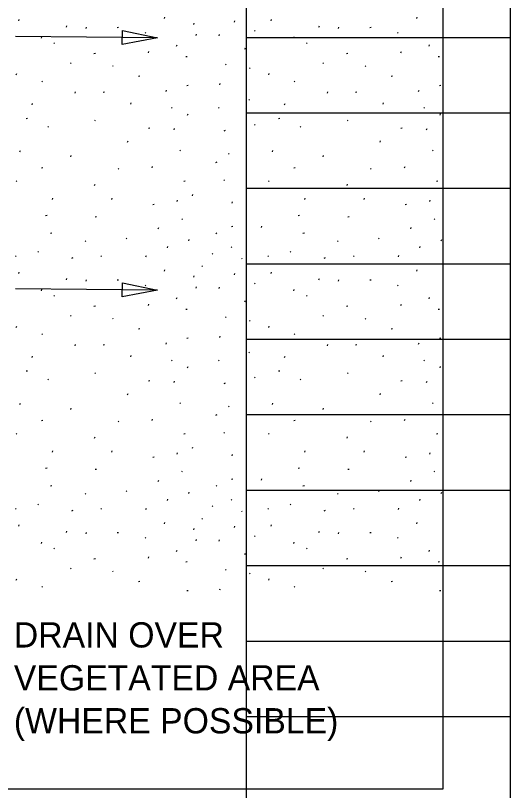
# Model space of a CAD drawing. Extents: x 0 to 34, y 0 to 22.
# Drawn here: x 8.482 to 10.32, y 5.465 to 8.341 of the extents above; entities that cross this region are included whole.
import ezdxf

# ---------------------------------------------------------------- set-up
doc = ezdxf.new("R2010")
doc.units = 0
for name, color, linetype in [('PF_P_Text', 7, 'Continuous'), ('SC_Scratch1', 7, 'Continuous'), ('SH_Text', 7, 'Continuous')]:
    doc.layers.add(name, color=color, linetype=linetype)

msp = doc.modelspace()

# ---------------------------------------------------------------- linework, layer by layer
at = {"layer": 'SC_Scratch1'}
for p, q in [((9.34, 0.98), (9.34, 21.14)), ((10.32, 0.98), (10.32, 21.14)), ((9.34, 8.26), (10.32, 8.26)), ((9.34, 7.98), (10.32, 7.98)), ((9.34, 7.7), (10.32, 7.7)), ((9.34, 7.42), (10.32, 7.42)), ((9.34, 7.14), (10.32, 7.14)), ((9.34, 6.86), (10.32, 6.86)), ((9.34, 6.58), (10.32, 6.58)), ((9.34, 6.3), (10.32, 6.3)), ((9.34, 6.02), (10.32, 6.02)), ((9.34, 5.74), (10.32, 5.74))]:
    msp.add_line(p, q, dxfattribs=at)
at = {"layer": 'SH_Text'}
for p, q in [((8.4939, 8.3209), (8.4956, 8.3258)), ((9.0346, 8.33), (9.0363, 8.3348)), ((9.1437, 8.3073), (9.1453, 8.3122)), ((9.2951, 8.3164), (9.2967, 8.3212)), ((9.4314, 8.3209), (9.433, 8.3258)), ((9.9721, 8.33), (9.9738, 8.3348)), ((8.6711, 8.2982), (8.6728, 8.3031)), ((8.7437, 8.2929), (8.7454, 8.2978)), ((8.8646, 8.2971), (8.8596, 8.296)), ((9.3714, 8.2829), (9.369, 8.2853)), ((9.6086, 8.2982), (9.6103, 8.3031)), ((9.6812, 8.2929), (9.6829, 8.2978)), ((9.8021, 8.2971), (9.7971, 8.296)), ((9.0096, 8.2582), (8.4817, 8.2629)), ((8.5779, 8.2567), (8.5795, 8.2615)), ((8.9655, 8.2761), (8.9631, 8.2786)), ((9.1528, 8.2665), (9.1544, 8.2714)), ((9.2382, 8.2657), (9.2399, 8.2706)), ((9.5154, 8.2567), (9.517, 8.2615)), ((9.903, 8.2761), (9.9006, 8.2786)), ((8.627, 8.2376), (8.6246, 8.24)), ((9.08, 8.2272), (9.0816, 8.2321)), ((9.5645, 8.2376), (9.5621, 8.24)), ((10.0175, 8.2272), (10.0191, 8.2321)), ((8.7783, 8.1997), (8.7732, 8.1986)), ((8.9755, 8.2023), (8.9771, 8.2071)), ((9.3336, 8.2159), (9.3353, 8.2207)), ((9.7158, 8.1997), (9.7107, 8.1986)), ((9.913, 8.2023), (9.9146, 8.2071)), ((9.1191, 8.1883), (9.114, 8.1872)), ((10.0566, 8.1883), (10.0515, 8.1872)), ((8.6884, 8.1628), (8.6859, 8.1652)), ((8.8451, 8.1514), (8.8427, 8.1539)), ((9.2646, 8.1582), (9.2622, 8.1607)), ((9.3532, 8.1446), (9.3508, 8.1471)), ((9.6259, 8.1628), (9.6234, 8.1652)), ((9.7826, 8.1514), (9.7802, 8.1539)), ((8.4847, 8.1207), (8.4864, 8.1255)), ((8.9441, 8.1158), (8.9391, 8.1147)), ((9.4222, 8.1207), (9.4239, 8.1255)), ((9.8816, 8.1158), (9.8766, 8.1147)), ((8.5816, 8.0948), (8.5791, 8.0972)), ((9.1236, 8.0818), (9.1186, 8.0807)), ((9.2405, 8.0844), (9.2421, 8.0893)), ((9.5191, 8.0948), (9.5166, 8.0972)), ((10.0611, 8.0818), (10.0561, 8.0807)), ((8.7028, 8.0527), (8.7045, 8.0575)), ((8.8123, 8.0569), (8.8073, 8.0558)), ((9.0414, 8.0595), (9.043, 8.0643)), ((9.6403, 8.0527), (9.642, 8.0575)), ((9.7498, 8.0569), (9.7448, 8.0558)), ((9.9789, 8.0595), (9.9805, 8.0643)), ((9.351, 8.0268), (9.3485, 8.0292)), ((8.5438, 8.0096), (8.5454, 8.0145)), ((8.9096, 8.0119), (8.9112, 8.0167)), ((9.0632, 7.9973), (9.0608, 7.9997)), ((9.2387, 7.9969), (9.2362, 7.9993)), ((9.4813, 8.0096), (9.4829, 8.0145)), ((9.8471, 8.0119), (9.8487, 8.0167)), ((10.0007, 7.9973), (9.9983, 7.9997)), ((9.121, 7.9718), (9.1226, 7.9767)), ((10.0585, 7.9718), (10.0601, 7.9767)), ((8.5261, 7.9594), (8.5211, 7.9583)), ((8.7792, 7.9497), (8.7768, 7.9521)), ((9.4636, 7.9594), (9.4586, 7.9583)), ((9.7167, 7.9497), (9.7143, 7.9521)), ((8.6043, 7.927), (8.6019, 7.9295)), ((8.9805, 7.9231), (8.9754, 7.922)), ((9.0709, 7.9167), (9.0725, 7.9215)), ((9.2607, 7.914), (9.2558, 7.9116)), ((9.3714, 7.9338), (9.369, 7.9363)), ((9.5418, 7.927), (9.5394, 7.9295)), ((9.918, 7.9231), (9.9129, 7.922)), ((10.0084, 7.9167), (10.01, 7.9215)), ((8.8982, 7.8713), (8.8999, 7.8762)), ((9.8357, 7.8713), (9.8374, 7.8762)), ((8.4984, 7.8351), (8.5, 7.8399)), ((9.095, 7.8386), (9.0926, 7.8411)), ((9.2753, 7.8264), (9.2729, 7.8288)), ((9.4359, 7.8351), (9.4375, 7.8399)), ((10.0325, 7.8386), (10.0301, 7.8411)), ((8.6869, 7.8169), (8.6886, 7.8218)), ((9.2289, 7.7971), (9.224, 7.7947)), ((9.6244, 7.8169), (9.6261, 7.8218)), ((8.5829, 7.7758), (8.5779, 7.7747)), ((8.8656, 7.7706), (8.8631, 7.7731)), ((8.9891, 7.7761), (8.9907, 7.781)), ((9.5204, 7.7758), (9.5154, 7.7747)), ((9.8031, 7.7706), (9.8006, 7.7731)), ((9.9266, 7.7761), (9.9282, 7.781)), ((8.4862, 7.7253), (8.4837, 7.7277)), ((8.7755, 7.7104), (8.7772, 7.7153)), ((9.1122, 7.7259), (9.1072, 7.7248)), ((9.2582, 7.7289), (9.2558, 7.7314)), ((9.4237, 7.7253), (9.4212, 7.7277)), ((9.713, 7.7104), (9.7147, 7.7153)), ((10.0497, 7.7259), (10.0447, 7.7248)), ((8.6188, 7.6583), (8.6204, 7.6631)), ((8.8392, 7.6583), (8.8408, 7.6631)), ((9.0823, 7.6515), (9.0839, 7.6563)), ((9.1391, 7.6726), (9.1408, 7.6775)), ((9.5563, 7.6583), (9.5579, 7.6631)), ((9.7767, 7.6583), (9.7783, 7.6631)), ((10.0198, 7.6515), (10.0214, 7.6563)), ((8.9964, 7.6398), (8.9914, 7.6387)), ((9.2859, 7.6447), (9.2876, 7.6495)), ((9.9339, 7.6398), (9.9288, 7.6387)), ((8.5988, 7.599), (8.5938, 7.5979)), ((8.7828, 7.5944), (8.7778, 7.5934)), ((9.5363, 7.599), (9.5313, 7.5979)), ((9.7203, 7.5944), (9.7153, 7.5934)), ((9.1018, 7.5848), (9.0994, 7.5872)), ((10.0393, 7.5848), (10.0369, 7.5872)), ((9.0118, 7.5495), (9.0135, 7.5543)), ((9.2886, 7.5582), (9.2836, 7.5571)), ((9.395, 7.554), (9.3966, 7.5589)), ((9.9493, 7.5495), (9.951, 7.5543)), ((8.617, 7.5332), (8.6119, 7.5322)), ((8.8951, 7.5122), (8.8927, 7.5147)), ((9.1255, 7.5049), (9.1271, 7.5097)), ((9.2289, 7.5316), (9.2265, 7.5341)), ((9.5545, 7.5332), (9.5494, 7.5322)), ((9.8326, 7.5122), (9.8302, 7.5147)), ((10.063, 7.5049), (10.0646, 7.5097)), ((8.743, 7.5024), (8.7406, 7.5048)), ((9.0459, 7.4792), (9.0475, 7.4841)), ((9.2851, 7.4805), (9.2826, 7.4829)), ((9.6805, 7.5024), (9.6781, 7.5048)), ((9.9834, 7.4792), (9.985, 7.4841)), ((8.4843, 7.4464), (8.4818, 7.4488)), ((8.5673, 7.4634), (8.5648, 7.4659)), ((8.8016, 7.4464), (8.7992, 7.4488)), ((8.9664, 7.4452), (8.968, 7.4501)), ((9.2143, 7.4561), (9.2118, 7.4586)), ((9.4218, 7.4464), (9.4193, 7.4488)), ((9.5048, 7.4634), (9.5023, 7.4659)), ((9.7391, 7.4464), (9.7367, 7.4488)), ((9.9039, 7.4452), (9.9055, 7.4501)), ((8.6942, 7.4415), (8.6893, 7.4391)), ((9.3241, 7.4366), (9.3217, 7.4391)), ((9.6317, 7.4415), (9.6268, 7.4391)), ((9.0346, 7.3925), (9.0363, 7.3973)), ((9.1732, 7.4122), (9.1752, 7.4112)), ((9.1752, 7.4112), (9.1762, 7.41)), ((9.9721, 7.3925), (9.9738, 7.3973)), ((8.4939, 7.3834), (8.4956, 7.3883)), ((8.6711, 7.3607), (8.6728, 7.3656)), ((9.1437, 7.3698), (9.1453, 7.3747)), ((9.2951, 7.3789), (9.2967, 7.3837)), ((9.4314, 7.3834), (9.433, 7.3883)), ((9.6086, 7.3607), (9.6103, 7.3656)), ((8.7437, 7.3554), (8.7454, 7.3603)), ((8.8646, 7.3596), (8.8596, 7.3585)), ((8.9655, 7.3386), (8.9631, 7.3411)), ((9.1528, 7.329), (9.1544, 7.3339)), ((9.3714, 7.3454), (9.369, 7.3478)), ((9.6812, 7.3554), (9.6829, 7.3603)), ((9.8021, 7.3596), (9.7971, 7.3585)), ((9.903, 7.3386), (9.9006, 7.3411)), ((9.0096, 7.3221), (8.4817, 7.3268)), ((8.5779, 7.3192), (8.5795, 7.324)), ((9.2382, 7.3282), (9.2399, 7.3331)), ((9.5154, 7.3192), (9.517, 7.324)), ((8.627, 7.3001), (8.6246, 7.3025)), ((9.08, 7.2897), (9.0816, 7.2946)), ((9.3336, 7.2784), (9.3353, 7.2832)), ((9.5645, 7.3001), (9.5621, 7.3025)), ((10.0175, 7.2897), (10.0191, 7.2946)), ((8.7783, 7.2622), (8.7732, 7.2611)), ((8.9755, 7.2648), (8.9771, 7.2696)), ((9.1191, 7.2508), (9.114, 7.2497)), ((9.7158, 7.2622), (9.7107, 7.2611)), ((9.913, 7.2648), (9.9146, 7.2696)), ((10.0566, 7.2508), (10.0515, 7.2497)), ((8.6884, 7.2253), (8.6859, 7.2277)), ((9.2646, 7.2207), (9.2622, 7.2232)), ((9.6259, 7.2253), (9.6234, 7.2277)), ((8.8451, 7.2139), (8.8427, 7.2164)), ((9.3532, 7.2071), (9.3508, 7.2096)), ((9.7826, 7.2139), (9.7802, 7.2164)), ((8.4847, 7.1832), (8.4864, 7.188)), ((8.9441, 7.1783), (8.9391, 7.1772)), ((9.4222, 7.1832), (9.4239, 7.188)), ((9.8816, 7.1783), (9.8766, 7.1772)), ((8.5816, 7.1573), (8.5791, 7.1597)), ((9.1236, 7.1443), (9.1186, 7.1432)), ((9.2405, 7.1469), (9.2421, 7.1518)), ((9.5191, 7.1573), (9.5166, 7.1597)), ((10.0611, 7.1443), (10.0561, 7.1432)), ((8.7028, 7.1152), (8.7045, 7.12)), ((8.8123, 7.1194), (8.8073, 7.1183)), ((9.0414, 7.122), (9.043, 7.1268)), ((9.6403, 7.1152), (9.642, 7.12)), ((9.7498, 7.1194), (9.7448, 7.1183)), ((9.9789, 7.122), (9.9805, 7.1268)), ((8.5438, 7.0721), (8.5454, 7.077)), ((8.9096, 7.0744), (8.9112, 7.0792)), ((9.351, 7.0893), (9.3485, 7.0917)), ((9.4813, 7.0721), (9.4829, 7.077)), ((9.8471, 7.0744), (9.8487, 7.0792)), ((9.0632, 7.0598), (9.0608, 7.0622)), ((9.2387, 7.0594), (9.2362, 7.0618)), ((10.0007, 7.0598), (9.9983, 7.0622)), ((8.5261, 7.0219), (8.5211, 7.0208)), ((9.121, 7.0343), (9.1226, 7.0392)), ((9.4636, 7.0219), (9.4586, 7.0208)), ((10.0585, 7.0343), (10.0601, 7.0392)), ((8.6043, 6.9895), (8.6019, 6.992)), ((8.7792, 7.0122), (8.7768, 7.0146)), ((9.3714, 6.9963), (9.369, 6.9988)), ((9.5418, 6.9895), (9.5394, 6.992)), ((9.7167, 7.0122), (9.7143, 7.0146)), ((8.9805, 6.9856), (8.9754, 6.9845)), ((9.0709, 6.9792), (9.0725, 6.984)), ((9.2607, 6.9765), (9.2558, 6.9741)), ((9.918, 6.9856), (9.9129, 6.9845)), ((10.0084, 6.9792), (10.01, 6.984)), ((8.8982, 6.9338), (8.8999, 6.9387)), ((9.8357, 6.9338), (9.8374, 6.9387)), ((8.4984, 6.8976), (8.5, 6.9024)), ((9.095, 6.9011), (9.0926, 6.9036)), ((9.4359, 6.8976), (9.4375, 6.9024)), ((10.0325, 6.9011), (10.0301, 6.9036)), ((8.6869, 6.8794), (8.6886, 6.8843)), ((9.2753, 6.8889), (9.2729, 6.8913)), ((9.6244, 6.8794), (9.6261, 6.8843)), ((9.2289, 6.8596), (9.224, 6.8572)), ((8.5829, 6.8383), (8.5779, 6.8372)), ((8.8656, 6.8331), (8.8631, 6.8356)), ((8.9891, 6.8386), (8.9907, 6.8435)), ((9.5204, 6.8383), (9.5154, 6.8372)), ((9.8031, 6.8331), (9.8006, 6.8356)), ((9.9266, 6.8386), (9.9282, 6.8435)), ((8.4862, 6.7878), (8.4837, 6.7902)), ((9.1122, 6.7884), (9.1072, 6.7873)), ((9.2582, 6.7914), (9.2558, 6.7939)), ((9.4237, 6.7878), (9.4212, 6.7902)), ((10.0497, 6.7884), (10.0447, 6.7873)), ((8.7755, 6.7729), (8.7772, 6.7778)), ((9.713, 6.7729), (9.7147, 6.7778)), ((9.1391, 6.7351), (9.1408, 6.74)), ((8.6188, 6.7208), (8.6204, 6.7256)), ((8.8392, 6.7208), (8.8408, 6.7256)), ((8.9964, 6.7023), (8.9914, 6.7012)), ((9.0823, 6.714), (9.0839, 6.7188)), ((9.2859, 6.7072), (9.2876, 6.712)), ((9.5563, 6.7208), (9.5579, 6.7256)), ((9.7767, 6.7208), (9.7783, 6.7256)), ((9.9339, 6.7023), (9.9288, 6.7012)), ((10.0198, 6.714), (10.0214, 6.7188)), ((8.5988, 6.6615), (8.5938, 6.6604)), ((8.7828, 6.6569), (8.7778, 6.6559)), ((9.1018, 6.6473), (9.0994, 6.6497)), ((9.5363, 6.6615), (9.5313, 6.6604)), ((9.7203, 6.6569), (9.7153, 6.6559)), ((10.0393, 6.6473), (10.0369, 6.6497)), ((9.0118, 6.612), (9.0135, 6.6168)), ((9.2886, 6.6207), (9.2836, 6.6196)), ((9.395, 6.6165), (9.3966, 6.6214)), ((9.9493, 6.612), (9.951, 6.6168)), ((8.617, 6.5957), (8.6119, 6.5947)), ((9.2289, 6.5941), (9.2265, 6.5966)), ((9.5545, 6.5957), (9.5494, 6.5947)), ((8.743, 6.5649), (8.7406, 6.5673)), ((8.8951, 6.5747), (8.8927, 6.5772)), ((9.1255, 6.5674), (9.1271, 6.5722)), ((9.6805, 6.5649), (9.6781, 6.5673)), ((9.8326, 6.5747), (9.8302, 6.5772)), ((10.063, 6.5674), (10.0646, 6.5722)), ((8.5673, 6.5259), (8.5648, 6.5284)), ((9.0459, 6.5417), (9.0475, 6.5466)), ((9.2851, 6.543), (9.2826, 6.5454)), ((9.5048, 6.5259), (9.5023, 6.5284)), ((9.9834, 6.5417), (9.985, 6.5466)), ((8.4843, 6.5089), (8.4818, 6.5113)), ((8.6942, 6.504), (8.6893, 6.5016)), ((8.8016, 6.5089), (8.7992, 6.5113)), ((8.9664, 6.5077), (8.968, 6.5126)), ((9.2143, 6.5186), (9.2118, 6.5211)), ((9.3241, 6.4991), (9.3217, 6.5016)), ((9.4218, 6.5089), (9.4193, 6.5113)), ((9.6317, 6.504), (9.6268, 6.5016)), ((9.7391, 6.5089), (9.7367, 6.5113)), ((9.9039, 6.5077), (9.9055, 6.5126)), ((9.1732, 6.4747), (9.1752, 6.4737)), ((9.1752, 6.4737), (9.1762, 6.4725)), ((8.4939, 6.4459), (8.4956, 6.4508)), ((9.0346, 6.455), (9.0363, 6.4598)), ((9.2951, 6.4414), (9.2967, 6.4462)), ((9.4314, 6.4459), (9.433, 6.4508)), ((9.9721, 6.455), (9.9738, 6.4598)), ((8.6711, 6.4232), (8.6728, 6.4281)), ((8.7437, 6.4179), (8.7454, 6.4228)), ((8.8646, 6.4221), (8.8596, 6.421)), ((9.1437, 6.4323), (9.1453, 6.4372)), ((9.6086, 6.4232), (9.6103, 6.4281)), ((9.6812, 6.4179), (9.6829, 6.4228)), ((9.8021, 6.4221), (9.7971, 6.421)), ((8.5779, 6.3817), (8.5795, 6.3865)), ((8.9655, 6.4011), (8.9631, 6.4036)), ((9.1528, 6.3915), (9.1544, 6.3964)), ((9.2382, 6.3907), (9.2399, 6.3956)), ((9.3714, 6.4079), (9.369, 6.4104)), ((9.5154, 6.3817), (9.517, 6.3865)), ((9.903, 6.4011), (9.9006, 6.4036)), ((8.627, 6.3626), (8.6246, 6.365)), ((9.08, 6.3522), (9.0816, 6.3571)), ((9.5645, 6.3626), (9.5621, 6.365)), ((10.0175, 6.3522), (10.0191, 6.3571)), ((8.9755, 6.3273), (8.9771, 6.3321)), ((9.3336, 6.3409), (9.3353, 6.3457)), ((9.913, 6.3273), (9.9146, 6.3321)), ((8.7783, 6.3247), (8.7732, 6.3236)), ((9.1191, 6.3133), (9.114, 6.3122)), ((9.7158, 6.3247), (9.7107, 6.3236)), ((10.0566, 6.3133), (10.0515, 6.3122)), ((8.6884, 6.2878), (8.6859, 6.2902)), ((8.8451, 6.2764), (8.8427, 6.2789)), ((9.2646, 6.2832), (9.2622, 6.2857)), ((9.3532, 6.2696), (9.3508, 6.2721)), ((9.6259, 6.2878), (9.6234, 6.2902)), ((9.7826, 6.2764), (9.7802, 6.2789)), ((8.4847, 6.2457), (8.4864, 6.2505)), ((8.9441, 6.2408), (8.9391, 6.2397)), ((9.4222, 6.2457), (9.4239, 6.2505)), ((9.8816, 6.2408), (9.8766, 6.2397)), ((8.5816, 6.2198), (8.5791, 6.2222)), ((9.2405, 6.2094), (9.2421, 6.2143)), ((9.5191, 6.2198), (9.5166, 6.2222)), ((9.1236, 6.2068), (9.1186, 6.2057)), ((10.0611, 6.2068), (10.0561, 6.2057))]:
    msp.add_line(p, q, dxfattribs=at)
msp.add_lwpolyline([(10.0688, 9.8619), (10.0688, 5.4707), (6.215, 5.4707), (6.215, 9.7403)], dxfattribs=at)
for points in [[(8.8786, 8.2856), (9.0096, 8.2582), (8.8781, 8.2331)], [(8.8786, 7.3495), (9.0096, 7.3221), (8.8781, 7.297)]]:
    msp.add_lwpolyline(points, close=True, dxfattribs=at)

# ---------------------------------------------------------------- texts
at = {"layer": 'PF_P_Text'}
for s, p in [('DRAIN OVER', (8.4756, 5.996)), ('VEGETATED AREA', (8.4756, 5.8367)), ('(WHERE POSSIBLE)', (8.4756, 5.6773))]:
    msp.add_text(s, height=0.09375, dxfattribs=at).set_placement(p)

doc.saveas('drawing.dxf')
